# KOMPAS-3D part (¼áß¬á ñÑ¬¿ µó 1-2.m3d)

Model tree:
1. Эскиз:1
2. Операция выдавливания:24
     Толщина стенки 2 = 14; Расстояние 1 = 0.6
3. Эскиз:22
4. Операция выдавливания:25
     Толщина стенки 1 = 7; Толщина стенки 2 = 6; Расстояние 1 = 0.6; Расстояние 2 = 0.6
5. Эскиз:23
6. Операция выдавливания:26
     Толщина стенки 1 = 6; Толщина стенки 2 = 6; Расстояние 1 = 0.6
7. Эскиз:26
8. Вырезать элемент выдавливания:3
     Толщина стенки 1 = 7; Расстояние 1 = 10
